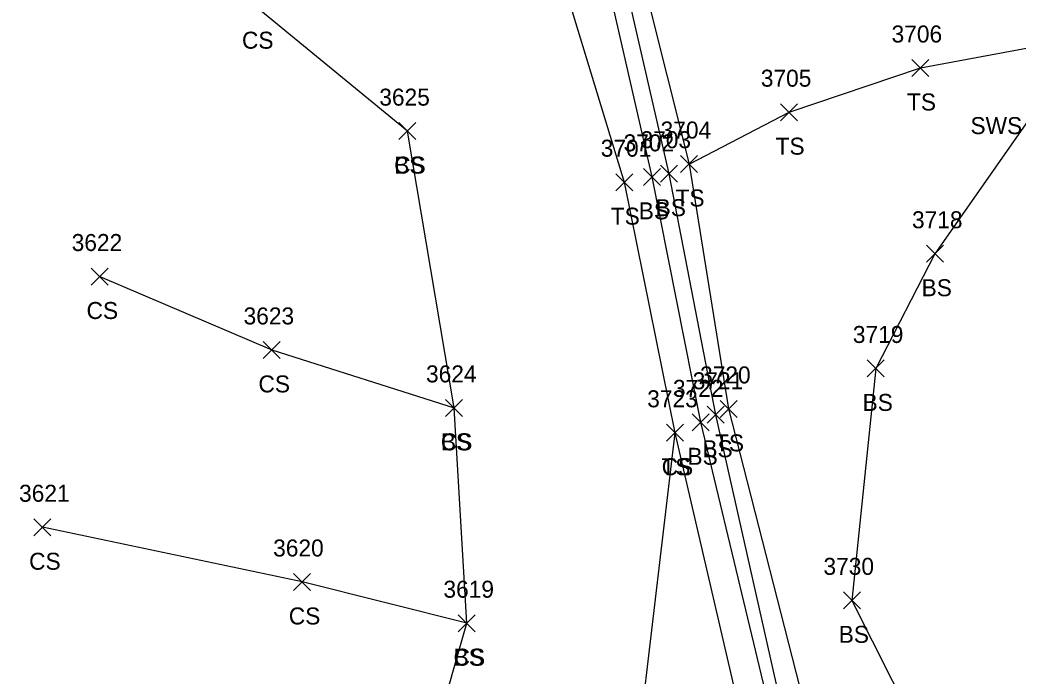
# Model space of a CAD drawing. Extents: x 49137 to 50946, y 9590 to 10709.
# Drawn here: x 49847.8 to 49965.3, y 10286.3 to 10363.6 of the extents above; entities that cross this region are included whole.
import ezdxf

# ---------------------------------------------------------------- set-up
doc = ezdxf.new("R2010")
doc.units = 0
for name, color, linetype in [('L_A', 7, 'Continuous'), ('L_I', 7, 'Continuous'), ('L_TIC', 7, 'Continuous'), ('LELB', 7, 'Continuous'), ('R_A', 7, 'Continuous')]:
    doc.layers.add(name, color=color, linetype=linetype)

msp = doc.modelspace()

# ---------------------------------------------------------------- linework, layer by layer
at = {"layer": 'L_TIC'}
for points in [[(49952.78, 10356.9), (49954.78, 10358.9)], [(49954.78, 10356.9), (49952.78, 10358.9)], [(49937.32, 10351.7), (49939.32, 10353.7)], [(49939.32, 10351.7), (49937.32, 10353.7)], [(49892.4, 10349.47), (49894.4, 10351.47)], [(49894.4, 10349.47), (49892.4, 10351.47)], [(49892.4, 10349.47), (49894.4, 10351.47)], [(49894.4, 10349.47), (49892.4, 10351.47)], [(49925.54, 10345.6), (49927.54, 10347.6)], [(49927.54, 10345.6), (49925.54, 10347.6)], [(49925.54, 10345.6), (49927.54, 10347.6)], [(49927.54, 10345.6), (49925.54, 10347.6)], [(49917.92, 10343.46), (49919.92, 10345.46)], [(49919.92, 10343.46), (49917.92, 10345.46)], [(49921.18, 10344.09), (49923.18, 10346.09)], [(49923.18, 10344.09), (49921.18, 10346.09)], [(49923.17, 10344.46), (49925.17, 10346.46)], [(49925.17, 10344.46), (49923.17, 10346.46)], [(49954.47, 10335.04), (49956.47, 10337.04)], [(49956.47, 10335.04), (49954.47, 10337.04)], [(49856.2, 10332.36), (49858.2, 10334.36)], [(49858.2, 10332.36), (49856.2, 10334.36)], [(49876.43, 10323.72), (49878.43, 10325.72)], [(49878.43, 10323.72), (49876.43, 10325.72)], [(49947.52, 10321.54), (49949.52, 10323.54)], [(49949.52, 10321.54), (49947.52, 10323.54)], [(49897.89, 10316.9), (49899.89, 10318.9)], [(49899.89, 10316.9), (49897.89, 10318.9)], [(49897.89, 10316.9), (49899.89, 10318.9)], [(49899.89, 10316.9), (49897.89, 10318.9)], [(49930.19, 10316.78), (49932.19, 10318.78)], [(49932.19, 10316.78), (49930.19, 10318.78)], [(49928.67, 10316.09), (49930.67, 10318.09)], [(49930.67, 10316.09), (49928.67, 10318.09)], [(49926.91, 10315.2), (49928.91, 10317.2)], [(49928.91, 10315.2), (49926.91, 10317.2)], [(49923.88, 10313.97), (49925.88, 10315.97)], [(49925.88, 10313.97), (49923.88, 10315.97)], [(49923.88, 10313.97), (49925.88, 10315.97)], [(49925.88, 10313.97), (49923.88, 10315.97)], [(49849.44, 10302.85), (49851.44, 10304.85)], [(49851.44, 10302.85), (49849.44, 10304.85)], [(49880, 10296.41), (49882, 10298.41)], [(49882, 10296.41), (49880, 10298.41)], [(49944.71, 10294.25), (49946.71, 10296.25)], [(49946.71, 10294.25), (49944.71, 10296.25)], [(49899.39, 10291.56), (49901.39, 10293.56)], [(49901.39, 10291.56), (49899.39, 10293.56)], [(49899.39, 10291.56), (49901.39, 10293.56)], [(49901.39, 10291.56), (49899.39, 10293.56)]]:
    msp.add_lwpolyline(points, dxfattribs=at)
at = {"layer": 'LELB'}
for points in [[(49903.91, 10403.07), (49911.31, 10397.95), (49908.98, 10377.05), (49918.92, 10344.46), (49924.88, 10314.97), (49933.87, 10276.3), (49940.89, 10262.56), (49945.47, 10244.99), (49948.91, 10239.74)], [(49919, 10397.71), (49918.47, 10395.67), (49914.7, 10377.7), (49922.18, 10345.09), (49927.91, 10316.2), (49937.09, 10277.78), (49944.81, 10264.42), (49950.08, 10244.28), (49954.67, 10238.49)], [(49920.18, 10395.53), (49916.78, 10377.62), (49924.17, 10345.46), (49929.67, 10317.09), (49938.45, 10278.05), (49946.47, 10265.1), (49955.29, 10243.85), (49957.39, 10237.87)], [(49921.91, 10391.69), (49918.73, 10377.87), (49926.54, 10346.6), (49931.19, 10317.78), (49940.87, 10279.88), (49949.17, 10266.57), (49958.68, 10242.13), (49960.7, 10237.06)], [(49893.4, 10350.47), (49875.49, 10365.17), (49851.58, 10380.41)], [(49926.54, 10346.6), (49938.32, 10352.7), (49953.78, 10357.9), (49973.01, 10361.49)], [(49968.85, 10355.12), (49955.47, 10336.04), (49948.52, 10322.54), (49945.71, 10295.25), (49955.23, 10276.32), (49969.26, 10262.53), (49976.79, 10237.9)], [(49864.15, 10241.05), (49887.63, 10251.66), (49893.27, 10267.55), (49900.39, 10292.56), (49898.89, 10317.9), (49893.4, 10350.47)], [(49857.2, 10333.36), (49877.43, 10324.72), (49898.89, 10317.9)], [(49924.88, 10314.97), (49920.74, 10280.13), (49907.45, 10259.09), (49925.33, 10245.46)], [(49900.39, 10292.56), (49881, 10297.41), (49850.44, 10303.85)]]:
    msp.add_lwpolyline(points, dxfattribs=at)

# ---------------------------------------------------------------- texts
at = {"layer": 'L_A'}
for s, p in [('CS', (49873.93, 10360.17)), ('TS', (49952.19, 10352.9)), ('TS', (49936.73, 10347.7)), ('CS', (49891.84, 10345.47)), ('BS', (49891.84, 10345.47)), ('TS', (49924.95, 10341.6)), ('TS', (49924.95, 10341.6)), ('BS', (49920.62, 10340.09)), ('BS', (49922.61, 10340.46)), ('TS', (49917.33, 10339.46)), ('BS', (49953.91, 10331.04)), ('CS', (49855.64, 10328.36)), ('CS', (49875.87, 10319.72)), ('BS', (49946.96, 10317.54)), ('CS', (49897.33, 10312.9)), ('BS', (49897.33, 10312.9)), ('BS', (49928.11, 10312.09)), ('TS', (49929.6, 10312.78)), ('BS', (49926.35, 10311.2)), ('TS', (49923.29, 10309.97)), ('CS', (49923.32, 10309.97)), ('CS', (49848.88, 10298.85)), ('CS', (49879.44, 10292.41)), ('BS', (49944.15, 10290.25)), ('CS', (49898.83, 10287.56)), ('BS', (49898.83, 10287.56))]:
    msp.add_text(s, height=2, dxfattribs=at).set_placement(p)
at = {"layer": 'L_I'}
for s, p in [('3706', (49950.38, 10360.9)), ('3705', (49934.99, 10355.7)), ('3625', (49890.09, 10353.47)), ('3625', (49890.09, 10353.47)), ('3704', (49923.2, 10349.6)), ('3704', (49923.2, 10349.6)), ('3703', (49920.83, 10348.46)), ('3701', (49916.15, 10347.46)), ('3702', (49918.84, 10348.09)), ('3718', (49952.78, 10339.04)), ('3622', (49853.89, 10336.36)), ('3623', (49874.12, 10327.72)), ('3719', (49945.82, 10325.54)), ('3624', (49895.59, 10320.9)), ('3624', (49895.59, 10320.9)), ('3721', (49926.97, 10320.09)), ('3720', (49927.84, 10320.78)), ('3722', (49924.65, 10319.2)), ('3723', (49921.62, 10317.97)), ('3723', (49921.62, 10317.97)), ('3621', (49847.7, 10306.85)), ('3620', (49877.6, 10300.41)), ('3730', (49942.36, 10298.25)), ('3619', (49897.64, 10295.56)), ('3619', (49897.64, 10295.56))]:
    msp.add_text(s, height=2, dxfattribs=at).set_placement(p)
at = {"layer": 'R_A'}
msp.add_text('SWS BS4 ST', height=2, dxfattribs=at).set_placement((49959.66, 10350.12))

doc.saveas('drawing.dxf')
